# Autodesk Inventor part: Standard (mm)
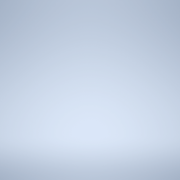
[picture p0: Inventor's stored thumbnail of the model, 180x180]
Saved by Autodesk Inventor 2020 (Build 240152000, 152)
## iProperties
Created: 2019-02
Part Number: Standard (mm)
Material: Ogólny
Document SubType Name: Modeling
Density: 1 g/cm^3
Appearance: Domyślna
Manager: www.cadconsulting.pl
Company: Fabian Stasiak CAD Consulting
Subject: Zbiór ćwiczeń. Autodesk Inventor 2020. Kurs podstawowy
Author: F.Stasiak
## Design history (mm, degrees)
